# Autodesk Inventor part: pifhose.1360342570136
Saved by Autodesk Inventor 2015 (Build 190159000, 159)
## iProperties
IsCustomPart: 1
Company: Parker Hannifin
Created: 2013-02
Material: Rubber
Description: Tömlő
Document SubType Name: Modeling
Standard: Parker
Designer: Marci
Manufacturer: Parker
Language: hu-HU
Size Designation: 1/4 - 5
Categories: <MemberInstance><Categories><Category DisplayName="Csővezetékek" InternalName="4347fa0f-2144-441d-94cd-e3e15c92b736" Mnemonic="TUBEANDPIPE"><CategoryParameter D
Stock Number: Parker hidraulikatömlő - No Skive 1/4
Density: 1 g/cm^3
Appearance: Rubber - Black - Version 1.1
NAME: PIPING: Parker Hydraulic Hose - No Skive
DATA: <meta><inlinegroups number="1" deflen="12.7"></inlinegroups><connections number="2"></connections><angles><a>3.14159265358979</a></angles></meta>
L: 22,374 in
PL: 22,374 in
RPL: 22,375 in
OPL: 22,374 in
ROPL: 22,375 in
Author: Marci
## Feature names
1. Sweep1
## Parameters: ID = 6.35 mm, OD = 14.986 mm, L = 568.2996 mm, PL = 568.2996 mm, Size_Designation = 2.5 mm, d6 = 0, RPL = 568.325 mm, OPL = 568.2996 mm, ROPL = 568.325 mm, d7 = 0
